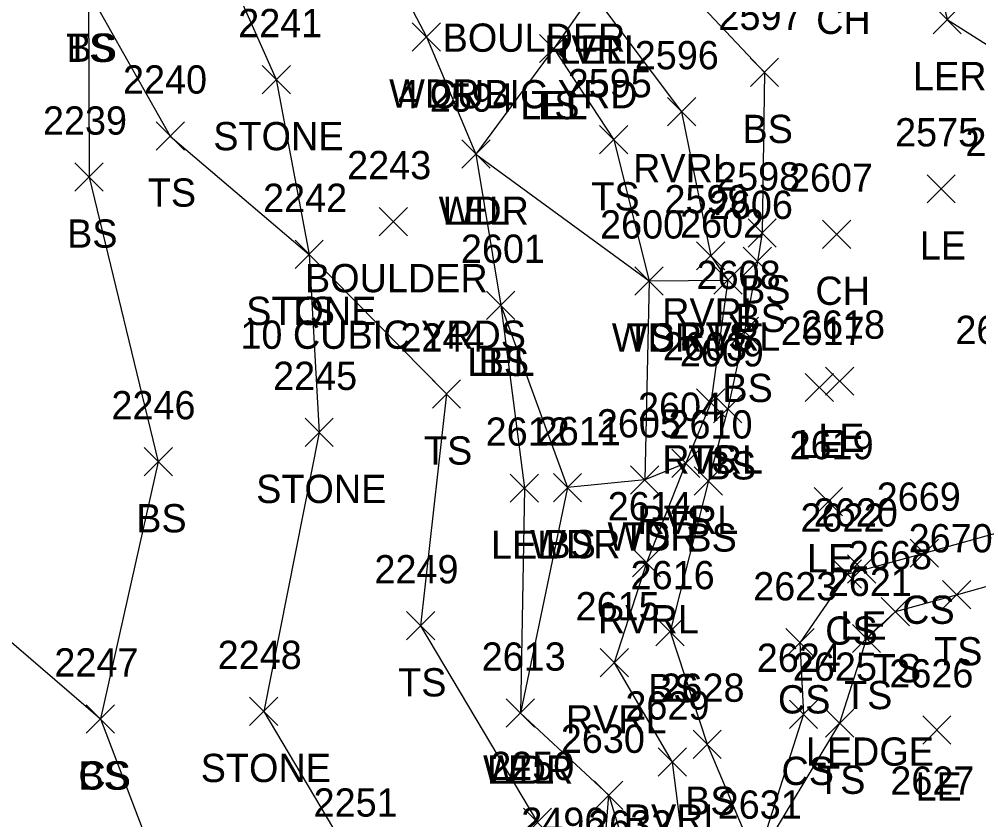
# Model space of a CAD drawing. Extents: x 1512665 to 1513714, y 110636 to 112816.
# Drawn here: x 1512998.3 to 1513066.2, y 110851.6 to 110908.3 of the extents above; entities that cross this region are included whole.
import ezdxf

# ---------------------------------------------------------------- set-up
doc = ezdxf.new("R2010")
doc.units = 0
for name, color, linetype in [('L_A', 7, 'Continuous'), ('L_C', 7, 'Continuous'), ('L_I', 7, 'Continuous'), ('L_TIC', 7, 'Continuous'), ('LARO', 7, 'Continuous'), ('LASF', 7, 'Continuous'), ('LAWA', 7, 'Continuous'), ('LAWE', 7, 'Continuous'), ('LELB', 7, 'Continuous')]:
    doc.layers.add(name, color=color, linetype=linetype)

msp = doc.modelspace()

# ---------------------------------------------------------------- linework, layer by layer
at = {"layer": 'L_TIC'}
for points in [[(1513062.95, 110907.226), (1513064.95, 110909.226)], [(1513064.95, 110907.226), (1513062.95, 110909.226)], [(1513026.098, 110905.993), (1513028.098, 110907.993)], [(1513028.098, 110905.993), (1513026.098, 110907.993)], [(1513035.107, 110905.177), (1513037.107, 110907.177)], [(1513037.107, 110905.177), (1513035.107, 110907.177)], [(1513035.107, 110905.177), (1513037.107, 110907.177)], [(1513037.107, 110905.177), (1513035.107, 110907.177)], [(1513050.022, 110903.489), (1513052.022, 110905.489)], [(1513052.022, 110903.489), (1513050.022, 110905.489)], [(1513015.469, 110902.978), (1513017.469, 110904.978)], [(1513017.469, 110902.978), (1513015.469, 110904.978)], [(1513044.154, 110900.707), (1513046.154, 110902.707)], [(1513046.154, 110900.707), (1513044.154, 110902.707)], [(1513007.968, 110898.986), (1513009.968, 110900.986)], [(1513009.968, 110898.986), (1513007.968, 110900.986)], [(1513039.355, 110898.721), (1513041.355, 110900.721)], [(1513041.355, 110898.721), (1513039.355, 110900.721)], [(1513029.598, 110897.706), (1513031.598, 110899.706)], [(1513031.598, 110897.706), (1513029.598, 110899.706)], [(1513029.598, 110897.706), (1513031.598, 110899.706)], [(1513031.598, 110897.706), (1513029.598, 110899.706)], [(1513002.224, 110896.085), (1513004.224, 110898.085)], [(1513004.224, 110896.085), (1513002.224, 110898.085)], [(1513062.522, 110895.25), (1513064.522, 110897.25)], [(1513064.522, 110895.25), (1513062.522, 110897.25)], [(1513023.746, 110892.932), (1513025.746, 110894.932)], [(1513025.746, 110892.932), (1513023.746, 110894.932)], [(1513049.857, 110892.132), (1513051.857, 110894.132)], [(1513051.857, 110892.132), (1513049.857, 110894.132)], [(1513055.134, 110892.04), (1513057.134, 110894.04)], [(1513057.134, 110892.04), (1513055.134, 110894.04)], [(1513017.795, 110890.616), (1513019.795, 110892.616)], [(1513019.795, 110890.616), (1513017.795, 110892.616)], [(1513017.795, 110890.616), (1513019.795, 110892.616)], [(1513019.795, 110890.616), (1513017.795, 110892.616)], [(1513046.212, 110890.511), (1513048.212, 110892.511)], [(1513048.212, 110890.511), (1513046.212, 110892.511)], [(1513049.523, 110890.119), (1513051.523, 110892.119)], [(1513051.523, 110890.119), (1513049.523, 110892.119)], [(1513041.856, 110888.732), (1513043.856, 110890.732)], [(1513043.856, 110888.732), (1513041.856, 110890.732)], [(1513041.856, 110888.732), (1513043.856, 110890.732)], [(1513043.856, 110888.732), (1513041.856, 110890.732)], [(1513047.431, 110888.794), (1513049.431, 110890.794)], [(1513049.431, 110888.794), (1513047.431, 110890.794)], [(1513047.431, 110888.794), (1513049.431, 110890.794)], [(1513049.431, 110888.794), (1513047.431, 110890.794)], [(1513031.354, 110887.014), (1513033.354, 110889.014)], [(1513033.354, 110887.014), (1513031.354, 110889.014)], [(1513031.354, 110887.014), (1513033.354, 110889.014)], [(1513033.354, 110887.014), (1513031.354, 110889.014)], [(1513048.6, 110885.164), (1513050.6, 110887.164)], [(1513050.6, 110885.164), (1513048.6, 110887.164)], [(1513055.341, 110881.643), (1513057.341, 110883.643)], [(1513057.341, 110881.643), (1513055.341, 110883.643)], [(1513053.903, 110881.196), (1513055.903, 110883.196)], [(1513055.903, 110881.196), (1513053.903, 110883.196)], [(1513027.514, 110880.739), (1513029.514, 110882.739)], [(1513029.514, 110880.739), (1513027.514, 110882.739)], [(1513046.218, 110880.108), (1513048.218, 110882.108)], [(1513048.218, 110880.108), (1513046.218, 110882.108)], [(1513046.218, 110880.108), (1513048.218, 110882.108)], [(1513048.218, 110880.108), (1513046.218, 110882.108)], [(1513047.42, 110879.687), (1513049.42, 110881.687)], [(1513049.42, 110879.687), (1513047.42, 110881.687)], [(1513018.504, 110878.021), (1513020.504, 110880.021)], [(1513020.504, 110878.021), (1513018.504, 110880.021)], [(1513007.118, 110875.945), (1513009.118, 110877.945)], [(1513009.118, 110875.945), (1513007.118, 110877.945)], [(1513044.453, 110875.836), (1513046.453, 110877.836)], [(1513046.453, 110875.836), (1513044.453, 110877.836)], [(1513044.453, 110875.836), (1513046.453, 110877.836)], [(1513046.453, 110875.836), (1513044.453, 110877.836)], [(1513033.026, 110874.074), (1513035.026, 110876.074)], [(1513035.026, 110874.074), (1513033.026, 110876.074)], [(1513036.08, 110874.115), (1513038.08, 110876.115)], [(1513038.08, 110874.115), (1513036.08, 110876.115)], [(1513036.08, 110874.115), (1513038.08, 110876.115)], [(1513038.08, 110874.115), (1513036.08, 110876.115)], [(1513041.543, 110874.66), (1513043.543, 110876.66)], [(1513043.543, 110874.66), (1513041.543, 110876.66)], [(1513041.543, 110874.66), (1513043.543, 110876.66)], [(1513043.543, 110874.66), (1513041.543, 110876.66)], [(1513046.052, 110874.583), (1513048.052, 110876.583)], [(1513048.052, 110874.583), (1513046.052, 110876.583)], [(1513054.544, 110873.12), (1513056.544, 110875.12)], [(1513056.544, 110873.12), (1513054.544, 110875.12)], [(1513061.324, 110869.473), (1513063.324, 110871.473)], [(1513063.324, 110869.473), (1513061.324, 110871.473)], [(1513041.669, 110868.798), (1513043.669, 110870.798)], [(1513043.669, 110868.798), (1513041.669, 110870.798)], [(1513055.876, 110867.998), (1513057.876, 110869.998)], [(1513057.876, 110867.998), (1513055.876, 110869.998)], [(1513055.876, 110867.998), (1513057.876, 110869.998)], [(1513057.876, 110867.998), (1513055.876, 110869.998)], [(1513056.898, 110868.357), (1513058.898, 110870.357)], [(1513058.898, 110868.357), (1513056.898, 110870.357)], [(1513063.615, 110866.532), (1513065.615, 110868.532)], [(1513065.615, 110866.532), (1513063.615, 110868.532)], [(1513059.286, 110865.336), (1513061.286, 110867.336)], [(1513061.286, 110865.336), (1513059.286, 110867.336)], [(1513025.687, 110864.337), (1513027.687, 110866.337)], [(1513027.687, 110864.337), (1513025.687, 110866.337)], [(1513043.341, 110863.923), (1513045.341, 110865.923)], [(1513045.341, 110863.923), (1513043.341, 110865.923)], [(1513057.241, 110863.438), (1513059.241, 110865.438)], [(1513059.241, 110863.438), (1513057.241, 110865.438)], [(1513057.241, 110863.438), (1513059.241, 110865.438)], [(1513059.241, 110863.438), (1513057.241, 110865.438)], [(1513052.53, 110863.133), (1513054.53, 110865.133)], [(1513054.53, 110863.133), (1513052.53, 110865.133)], [(1513039.392, 110861.719), (1513041.392, 110863.719)], [(1513041.392, 110861.719), (1513039.392, 110863.719)], [(1513014.581, 110858.279), (1513016.581, 110860.279)], [(1513016.581, 110858.279), (1513014.581, 110860.279)], [(1513032.742, 110858.16), (1513034.742, 110860.16)], [(1513034.742, 110858.16), (1513032.742, 110860.16)], [(1513032.742, 110858.16), (1513034.742, 110860.16)], [(1513034.742, 110858.16), (1513032.742, 110860.16)], [(1513052.783, 110858.074), (1513054.783, 110860.074)], [(1513054.783, 110858.074), (1513052.783, 110860.074)], [(1513003.025, 110857.747), (1513005.025, 110859.747)], [(1513005.025, 110857.747), (1513003.025, 110859.747)], [(1513003.025, 110857.747), (1513005.025, 110859.747)], [(1513005.025, 110857.747), (1513003.025, 110859.747)], [(1513055.336, 110857.446), (1513057.336, 110859.446)], [(1513057.336, 110857.446), (1513055.336, 110859.446)], [(1513062.217, 110856.971), (1513064.217, 110858.971)], [(1513064.217, 110856.971), (1513062.217, 110858.971)], [(1513045.966, 110855.959), (1513047.966, 110857.959)], [(1513047.966, 110855.959), (1513045.966, 110857.959)], [(1513043.491, 110854.698), (1513045.491, 110856.698)], [(1513045.491, 110854.698), (1513043.491, 110856.698)], [(1513039.001, 110852.344), (1513041.001, 110854.344)], [(1513041.001, 110852.344), (1513039.001, 110854.344)], [(1513039.001, 110852.344), (1513041.001, 110854.344)], [(1513041.001, 110852.344), (1513039.001, 110854.344)], [(1513039.001, 110852.344), (1513041.001, 110854.344)], [(1513041.001, 110852.344), (1513039.001, 110854.344)], [(1513033.959, 110850.424), (1513035.959, 110852.424)], [(1513035.959, 110850.424), (1513033.959, 110852.424)]]:
    msp.add_lwpolyline(points, dxfattribs=at)
at = {"layer": 'LARO'}
for points in [[(1513054.78, 110925.922), (1513051.542, 110923.521), (1513042.371, 110918.213), (1513037.26, 110919.748), (1513038.859, 110910.101), (1513036.107, 110906.177), (1513030.598, 110898.706), (1513032.354, 110888.014), (1513034.026, 110875.074), (1513033.742, 110859.16), (1513040.001, 110853.344), (1513041.845, 110847.279), (1513041.351, 110841.628), (1513042.362, 110832.471), (1513042.539, 110822.433), (1513049.445, 110822.774)], [(1513062.377, 110914.721), (1513063.95, 110908.226), (1513076.095, 110900.544), (1513081.142, 110899.638), (1513083.533, 110896.731), (1513087.45, 110887.426), (1513089.949, 110869.067), (1513089.4, 110858.27), (1513090.026, 110849.208)]]:
    msp.add_lwpolyline(points, dxfattribs=at)
at = {"layer": 'LASF'}
msp.add_lwpolyline([(1513011.02, 110916.269), (1513016.469, 110903.978), (1513018.795, 110891.616), (1513019.504, 110879.021), (1513015.581, 110859.279), (1513021.804, 110848.835), (1513037.123, 110847.472)], dxfattribs=at)
at = {"layer": 'LAWA'}
for points in [[(1512977.183, 111087.039), (1512979.223, 111069.381), (1512984.419, 111047.271), (1512989.626, 111015.623), (1512994.847, 110988.4), (1512997.955, 110959.712), (1513004.768, 110944.172), (1513009.334, 110931.387), (1513020.981, 110918.633), (1513027.098, 110906.993), (1513030.598, 110898.706), (1513042.856, 110889.732), (1513042.543, 110875.66), (1513037.08, 110875.115), (1513033.742, 110859.16), (1513040.001, 110853.344)], [(1512988.199, 110800.659), (1513000.869, 110793.798), (1513013.264, 110785.095), (1513028.637, 110777.265), (1513031.778, 110776.166), (1513035.849, 110774.486), (1513038.334, 110774.274), (1513040.786, 110775.756), (1513040.029, 110778.791), (1513034.839, 110783.794), (1513031.373, 110791.45), (1513032.455, 110794.874), (1513030.687, 110802.22), (1513024.783, 110806.061), (1513019.321, 110811.594), (1513012.859, 110814.122), (1513012.233, 110818.887), (1513011.96, 110820.134), (1513029.824, 110821.619), (1513035.802, 110824.023), (1513038.307, 110832.035), (1513040.001, 110853.344)]]:
    msp.add_lwpolyline(points, dxfattribs=at)
at = {"layer": 'LAWE'}
msp.add_lwpolyline([(1513038.859, 110910.101), (1513045.154, 110901.707), (1513047.212, 110891.511), (1513048.431, 110889.794), (1513047.218, 110881.108), (1513045.453, 110876.836), (1513042.669, 110869.798), (1513040.392, 110862.719), (1513044.491, 110855.698), (1513046.304, 110841.49), (1513047.55, 110833.011), (1513046.481, 110826.49), (1513049.445, 110822.774), (1513049.569, 110818.823), (1513051.896, 110813.02), (1513060.202, 110802.398), (1513061.457, 110797.578)], dxfattribs=at)
at = {"layer": 'LELB'}
for points in [[(1512980.856, 111021.959), (1512966.161, 111016.967), (1512966.081, 111012.924), (1512971.64, 110991.754), (1512974.661, 110979.717), (1512973.513, 110967.07), (1512980.172, 110961.827), (1512987.448, 110934.998), (1512995.771, 110918.802), (1513003.18, 110910.234), (1513008.968, 110899.986), (1513018.795, 110891.616), (1513028.514, 110881.739), (1513026.687, 110865.337), (1513034.959, 110851.424)], [(1513042.359, 110913.678), (1513051.022, 110904.489), (1513050.857, 110893.132), (1513050.523, 110891.119), (1513049.6, 110886.164), (1513048.42, 110880.687), (1513047.052, 110875.583), (1513044.341, 110864.923), (1513046.966, 110856.959), (1513050.448, 110848.687), (1513058.822, 110841.505), (1513059.882, 110834.26), (1513060.074, 110831.468), (1513057.324, 110827.592), (1513055.626, 110827.804), (1513053.809, 110825.173), (1513053.571, 110819.742), (1513054.452, 110815.943), (1513058.433, 110815.223), (1513066.813, 110810.517), (1513067.833, 110807.075), (1513066.435, 110793.533), (1513062.103, 110786.67)], [(1513003.18, 110910.234), (1513003.224, 110897.085), (1513008.118, 110876.945), (1513004.025, 110858.747), (1513009.426, 110844.577), (1513003.953, 110835.587)], [(1513036.107, 110906.177), (1513040.355, 110899.721), (1513042.856, 110889.732), (1513048.431, 110889.794), (1513047.218, 110881.108), (1513045.453, 110876.836), (1513042.543, 110875.66)], [(1513056.876, 110868.998), (1513062.324, 110870.473), (1513071.52, 110873.054), (1513067.839, 110882.274), (1513071.224, 110894.733)], [(1513058.241, 110864.438), (1513060.286, 110866.336), (1513064.615, 110867.532), (1513073.142, 110869.938), (1513074.579, 110873.16), (1513070.662, 110883.136), (1513071.224, 110894.733)], [(1513032.354, 110888.014), (1513037.08, 110875.115)], [(1512990.903, 110870.015), (1513004.025, 110858.747)], [(1513056.876, 110868.998), (1513053.53, 110864.133), (1513053.783, 110859.074), (1513050.448, 110848.687), (1513046.304, 110841.49)], [(1513058.241, 110864.438), (1513056.336, 110858.446), (1513050.448, 110848.687), (1513053.381, 110841.536), (1513053.413, 110833.702), (1513052.932, 110827.898), (1513052.052, 110820.1), (1513051.896, 110813.02), (1513056.427, 110812.788), (1513056.427, 110809.608), (1513060.202, 110802.398), (1513059.911, 110795.058), (1513058.942, 110787.974), (1513057.337, 110783.187), (1513062.127, 110778.714), (1513067.7, 110773.015), (1513071.533, 110768.714), (1513070.983, 110761.956)]]:
    msp.add_lwpolyline(points, dxfattribs=at)

# ---------------------------------------------------------------- texts
at = {"layer": 'L_A'}
for s, p in [('CH', (1513054.679, 110907.206)), ('BOULDER', (1513028.244, 110905.947)), ('TS', (1513001.59, 110905.234)), ('BS', (1513001.621, 110905.234)), ('RVRL', (1513035.426, 110905.101)), ('LEL', (1513036.497, 110905.101)), ('LER', (1513061.532, 110903.226)), ('WDR', (1513024.46, 110901.993)), ('LEL', (1513033.744, 110901.177)), ('TS', (1513034.516, 110901.177)), ('BS', (1513049.463, 110899.489)), ('STONE', (1513012.012, 110898.978)), ('RVRL', (1513041.721, 110896.707)), ('TS', (1513007.377, 110894.986)), ('TS', (1513038.764, 110894.721)), ('WDR', (1513027.96, 110893.706)), ('LEL', (1513028.236, 110893.706)), ('BS', (1513001.665, 110892.085)), ('LE', (1513062.01, 110891.25)), ('BOULDER', (1513018.502, 110888.932)), ('BS', (1513049.298, 110888.132)), ('CH', (1513054.622, 110888.04)), ('STONE', (1513014.338, 110886.616)), ('TS', (1513017.204, 110886.616)), ('RVRL', (1513043.779, 110886.511)), ('BS', (1513048.964, 110886.119)), ('WDR', (1513040.218, 110884.732)), ('TS', (1513041.265, 110884.732)), ('RVRL', (1513044.998, 110884.794)), ('TS', (1513046.841, 110884.794)), ('LEL', (1513029.991, 110883.014)), ('BS', (1513030.795, 110883.014)), ('BS', (1513048.041, 110881.164)), ('LE', (1513054.829, 110877.643)), ('LE', (1513053.391, 110877.196)), ('TS', (1513026.923, 110876.739)), ('RVRL', (1513043.785, 110876.108)), ('TS', (1513045.628, 110876.108)), ('BS', (1513046.861, 110875.687)), ('STONE', (1513015.047, 110874.021)), ('BS', (1513006.559, 110871.945)), ('RVRL', (1513042.02, 110871.836)), ('TS', (1513043.863, 110871.836)), ('TS', (1513040.953, 110870.66)), ('LEL', (1513031.664, 110870.074)), ('WDR', (1513034.442, 110870.115)), ('BS', (1513035.52, 110870.115)), ('WDR', (1513039.906, 110870.66)), ('BS', (1513045.493, 110870.583)), ('LE', (1513054.032, 110869.12)), ('CS', (1513060.765, 110865.473)), ('RVRL', (1513039.236, 110864.798)), ('CS', (1513055.317, 110863.998)), ('CS', (1513055.317, 110863.998)), ('LE', (1513056.386, 110864.357)), ('TS', (1513063.024, 110862.532)), ('TS', (1513058.696, 110861.336)), ('TS', (1513025.097, 110860.337)), ('BS', (1513042.782, 110859.923)), ('CS', (1513051.971, 110859.133)), ('TS', (1513056.651, 110859.438)), ('TS', (1513056.651, 110859.438)), ('RVRL', (1513036.959, 110857.719)), ('CS', (1513002.465, 110853.747)), ('BS', (1513002.465, 110853.747)), ('STONE', (1513011.124, 110854.279)), ('WDR', (1513031.104, 110854.16)), ('LEL', (1513031.38, 110854.16)), ('CS', (1513052.224, 110854.074)), ('TS', (1513054.746, 110853.446)), ('LE', (1513061.705, 110852.971)), ('BS', (1513045.407, 110851.959)), ('RVRL', (1513041.058, 110850.698))]:
    msp.add_text(s, height=2, dxfattribs=at).set_placement(p)
at = {"layer": 'L_C'}
for s, p in [('4 CUBIC YRD', (1513025.094, 110901.947)), ('10 CUBIC YRDS', (1513013.927, 110884.932)), ('LEDGE', (1513053.942, 110855.438)), ('LEDGE', (1513053.942, 110855.438))]:
    msp.add_text(s, height=2, dxfattribs=at).set_placement(p)
at = {"layer": 'L_I'}
for s, p in [('2597', (1513047.762, 110907.489)), ('2241', (1513013.776, 110906.978)), ('2596', (1513041.84, 110904.707)), ('2240', (1513005.621, 110902.986)), ('2595', (1513037.095, 110902.721)), ('2594', (1513027.338, 110901.706)), ('2594', (1513027.338, 110901.706)), ('2239', (1512999.956, 110900.085)), ('2575', (1513060.262, 110899.25)), ('2574', (1513065.246, 110898.574)), ('2243', (1513021.486, 110896.932)), ('2598', (1513047.597, 110896.132)), ('2607', (1513052.748, 110896.04)), ('2242', (1513015.535, 110894.616)), ('2242', (1513015.535, 110894.616)), ('2599', (1513043.944, 110894.511)), ('2606', (1513047.082, 110894.119)), ('2600', (1513039.383, 110892.732)), ('2600', (1513039.383, 110892.732)), ('2602', (1513045.045, 110892.794)), ('2602', (1513045.045, 110892.794)), ('2601', (1513029.535, 110891.014)), ('2601', (1513029.535, 110891.014)), ('2608', (1513046.214, 110889.164)), ('2618', (1513053.601, 110885.643)), ('2617', (1513052.162, 110885.196)), ('2675', (1513064.532, 110885.274)), ('2244', (1513025.254, 110884.739)), ('2603', (1513043.832, 110884.108)), ('2603', (1513043.832, 110884.108)), ('2609', (1513045.026, 110883.687)), ('2245', (1513016.244, 110882.021)), ('2246', (1513004.803, 110879.945)), ('2604', (1513042.068, 110879.836)), ('2604', (1513042.068, 110879.836)), ('2611', (1513034.906, 110878.115)), ('2611', (1513034.906, 110878.115)), ('2605', (1513039.157, 110878.66)), ('2605', (1513039.157, 110878.66)), ('2610', (1513044.225, 110878.583)), ('2612', (1513031.286, 110878.074)), ('2619', (1513052.796, 110877.12)), ('2669', (1513058.962, 110873.473)), ('2614', (1513039.928, 110872.798)), ('2622', (1513053.569, 110871.998)), ('2622', (1513053.569, 110871.998)), ('2620', (1513054.505, 110872.357)), ('2670', (1513061.221, 110870.532)), ('2668', (1513056.932, 110869.336)), ('2249', (1513023.419, 110868.337)), ('2616', (1513041.545, 110867.923)), ('2621', (1513055.501, 110867.438)), ('2621', (1513055.501, 110867.438)), ('2623', (1513050.223, 110867.133)), ('2615', (1513037.652, 110865.719)), ('2248', (1513012.321, 110862.279)), ('2613', (1513031.002, 110862.16)), ('2613', (1513031.002, 110862.16)), ('2624', (1513050.476, 110862.074)), ('2247', (1513000.765, 110861.747)), ('2247', (1513000.765, 110861.747)), ('2625', (1513053.029, 110861.446)), ('2626', (1513059.854, 110860.971)), ('2628', (1513043.659, 110859.959)), ('2629', (1513041.176, 110858.698)), ('2630', (1513036.607, 110856.344)), ('2630', (1513036.607, 110856.344)), ('2630', (1513036.607, 110856.344)), ('2250', (1513031.612, 110854.424)), ('2627', (1513059.924, 110853.384)), ('2251', (1513019.111, 110851.835)), ('2631', (1513047.708, 110851.687)), ('2631', (1513047.708, 110851.687)), ('2631', (1513047.708, 110851.687)), ('2496', (1513033.808, 110850.472)), ('2496', (1513033.808, 110850.472)), ('2632', (1513038.538, 110850.279))]:
    msp.add_text(s, height=2, dxfattribs=at).set_placement(p)

doc.saveas('drawing.dxf')
